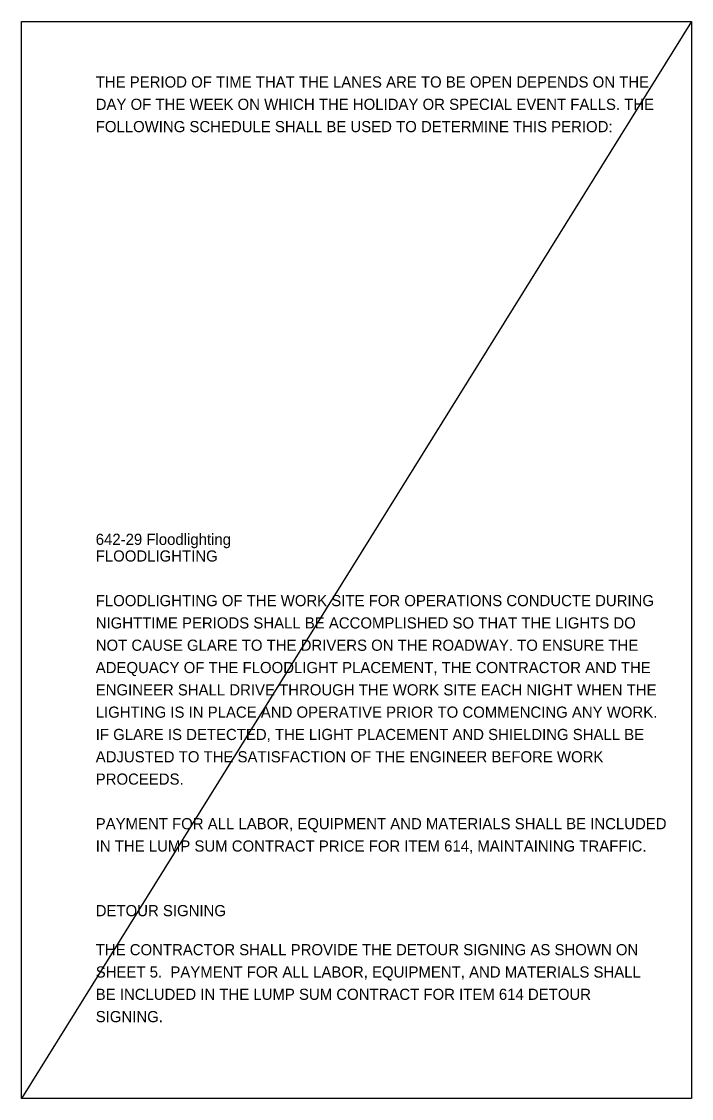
# Model space of a CAD drawing. Extents: x -9 to 36.8, y 0 to 22.
# Drawn here: x -9.02 to -0.62, y 4.11 to 17.63 of the extents above; entities that cross this region are included whole.
import ezdxf

# ---------------------------------------------------------------- set-up
doc = ezdxf.new("R2010")
doc.units = 0
doc.layers.add('SC_Scratch1', color=7, linetype='Continuous')
doc.layers.add('SH_Text', color=7, linetype='Continuous')

msp = doc.modelspace()

# ---------------------------------------------------------------- linework, layer by layer
at = {"layer": 'SC_Scratch1'}
msp.add_line((-0.618, 17.628), (-9.018, 4.113), dxfattribs=at)
msp.add_lwpolyline([(-9.018, 17.628), (-0.618, 17.628), (-0.618, 4.113), (-9.018, 4.113)], close=True, dxfattribs=at)

# ---------------------------------------------------------------- texts
for s, p in [('THE PERIOD OF TIME THAT THE LANES ARE TO BE OPEN DEPENDS ON THE ', (-8.088, 16.8)), ('DAY OF THE WEEK ON WHICH THE HOLIDAY OR SPECIAL EVENT FALLS. THE ', (-8.088, 16.52)), ('FOLLOWING SCHEDULE SHALL BE USED TO DETERMINE THIS PERIOD:', (-8.088, 16.24)), ('642-29 Floodlighting', (-8.088, 11.06))]:
    msp.add_text(s, height=0.14, dxfattribs=at).set_placement(p)
at = {"layer": 'SH_Text'}
for s, p in [('FLOODLIGHTING', (-8.088, 10.851)), ('FLOODLIGHTING OF THE WORK SITE FOR OPERATIONS CONDUCTE DURING ', (-8.088, 10.291)), ('NIGHTTIME PERIODS SHALL BE ACCOMPLISHED SO THAT THE LIGHTS DO ', (-8.088, 10.011)), ('NOT CAUSE GLARE TO THE DRIVERS ON THE ROADWAY. TO ENSURE THE ', (-8.088, 9.731)), ('ADEQUACY OF THE FLOODLIGHT PLACEMENT, THE CONTRACTOR AND THE ', (-8.088, 9.451)), ('ENGINEER SHALL DRIVE THROUGH THE WORK SITE EACH NIGHT WHEN THE ', (-8.088, 9.171)), ('LIGHTING IS IN PLACE AND OPERATIVE PRIOR TO COMMENCING ANY WORK. ', (-8.088, 8.891)), ('IF GLARE IS DETECTED, THE LIGHT PLACEMENT AND SHIELDING SHALL BE ', (-8.088, 8.611)), ('ADJUSTED TO THE SATISFACTION OF THE ENGINEER BEFORE WORK ', (-8.088, 8.331)), ('PROCEEDS.', (-8.088, 8.051)), ('PAYMENT FOR ALL LABOR, EQUIPMENT AND MATERIALS SHALL BE INCLUDED ', (-8.088, 7.491)), ('IN THE LUMP SUM CONTRACT PRICE FOR ITEM 614, MAINTAINING TRAFFIC.', (-8.088, 7.211)), ('DETOUR SIGNING', (-8.088, 6.4)), ('THE CONTRACTOR SHALL PROVIDE THE DETOUR SIGNING AS SHOWN ON ', (-8.088, 5.91)), ('SHEET 5.  PAYMENT FOR ALL LABOR, EQUIPMENT, AND MATERIALS SHALL ', (-8.088, 5.63)), ('BE INCLUDED IN THE LUMP SUM CONTRACT FOR ITEM 614 DETOUR ', (-8.088, 5.35)), ('SIGNING.', (-8.088, 5.07))]:
    msp.add_text(s, height=0.14, dxfattribs=at).set_placement(p)

doc.saveas('drawing.dxf')
